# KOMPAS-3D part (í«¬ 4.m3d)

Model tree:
1. Эскиз:1
2. Операция выдавливания:1
     Расстояние 1 = 3
3. Эскиз:2
4. Операция выдавливания:2
     Расстояние 1 = 78
5. Эскиз:3
6. Операция выдавливания:3
     Расстояние 1 = 3
7. Эскиз:4
8. Операция выдавливания:4
     Расстояние 1 = 4
9. Эскиз:5
10. Операция выдавливания:5
     Расстояние 1 = 4
11. Эскиз:6
12. Вырезать элемент выдавливания:1
     Расстояние 1 = 100
